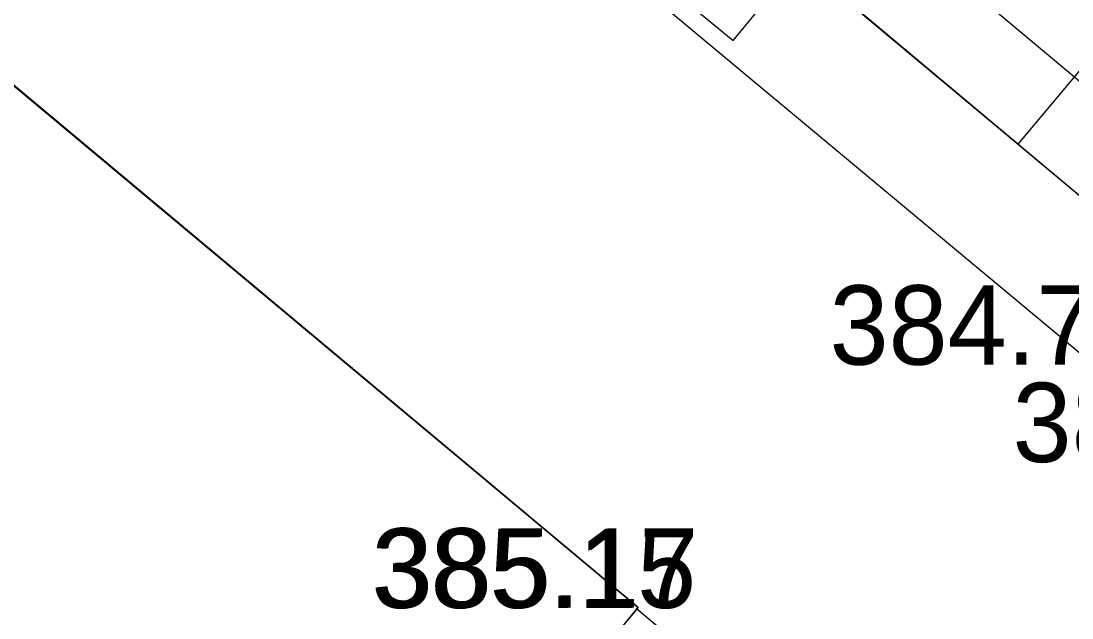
# Model space of a CAD drawing. Extents: x -438233 to -437334, y -1133133 to -1132623.
# Drawn here: x -438097.02 to -438087.09, y -1133000.68 to -1132995.04 of the extents above; entities that cross this region are included whole.
import ezdxf

# ---------------------------------------------------------------- set-up
doc = ezdxf.new("R2010")
doc.units = 0
for name, color, linetype in [('Vrstva 1', 7, 'Continuous'), ('Vrstva 10', 7, 'Continuous'), ('Vrstva 27', 7, 'Continuous'), ('Vrstva 3', 7, 'Continuous'), ('Vrstva 5', 7, 'Continuous'), ('Vrstva 50', 7, 'Continuous'), ('Vrstva 55', 7, 'Continuous')]:
    doc.layers.add(name, color=color, linetype=linetype)

msp = doc.modelspace()

# ---------------------------------------------------------------- linework, layer by layer
at = {"layer": 'Vrstva 1'}
for p, q in [((-438101.2096, -1132984.7999), (-438075.9136, -1133005.9921)), ((-438084.7135, -1132992.7493), (-438087.6034, -1132996.1988)), ((-438091.21, -1133000.582), (-438091.21, -1133000.582)), ((-438091.21, -1133000.582), (-438090.1267, -1133001.4895)), ((-438091.189, -1133000.578), (-438091.189, -1133000.578))]:
    msp.add_line(p, q, dxfattribs=at)
at = {"layer": 'Vrstva 10'}
msp.add_lwpolyline([(-438136.916, -1132976.04), (-438130.815, -1132968.777), (-438110.909, -1132985.383), (-438109.206, -1132983.342), (-438101.698, -1132989.616), (-438102.771, -1132990.9), (-438091.189, -1133000.578), (-438097.908, -1133008.583)], close=True, dxfattribs=at)
msp.add_lwpolyline([(-438106.458, -1132981.967), (-438090.957, -1132994.89), (-438086.882, -1132998.283), (-438085.153, -1132999.203), (-438079.851, -1133001.541), (-438076.272, -1133002.948)], dxfattribs=at)
at = {"layer": 'Vrstva 27'}
msp.add_lwpolyline([(-438090.68, -1132994.903), (-438090.293, -1132995.22), (-438089.976, -1132994.833), (-438090.363, -1132994.516)], close=True, dxfattribs=at)
at = {"layer": 'Vrstva 5'}
for p, q in [((-438091.189, -1133000.578), (-438102.771, -1132990.9)), ((-438097.908, -1133008.583), (-438091.189, -1133000.578))]:
    msp.add_line(p, q, dxfattribs=at)
at = {"layer": 'Vrstva 50'}
msp.add_lwpolyline([(-438098.3197, -1132981.3504), (-438073.0253, -1133002.5413), (-438075.9152, -1133005.9908), (-438101.2096, -1132984.7999)], close=True, dxfattribs=at)
at = {"layer": 'Vrstva 55'}
msp.add_lwpolyline([(-438074.9586, -1133013.6101), (-438076.856, -1133009.846), (-438083.298, -1132998.719), (-438115.192, -1132972.054), (-438146.469, -1132953.711), (-438176.9, -1132931.48)], dxfattribs=at)

# ---------------------------------------------------------------- texts
at = {"layer": 'Vrstva 3'}
for s, p in [('384.76 ', (-438089.382, -1132998.283)), ('384.70 ', (-438087.653, -1132999.203)), ('385.15 ', (-438093.71, -1133000.582)), ('385.17 ', (-438093.689, -1133000.578))]:
    msp.add_text(s, height=0.75, dxfattribs=at).set_placement(p)

doc.saveas('drawing.dxf')
